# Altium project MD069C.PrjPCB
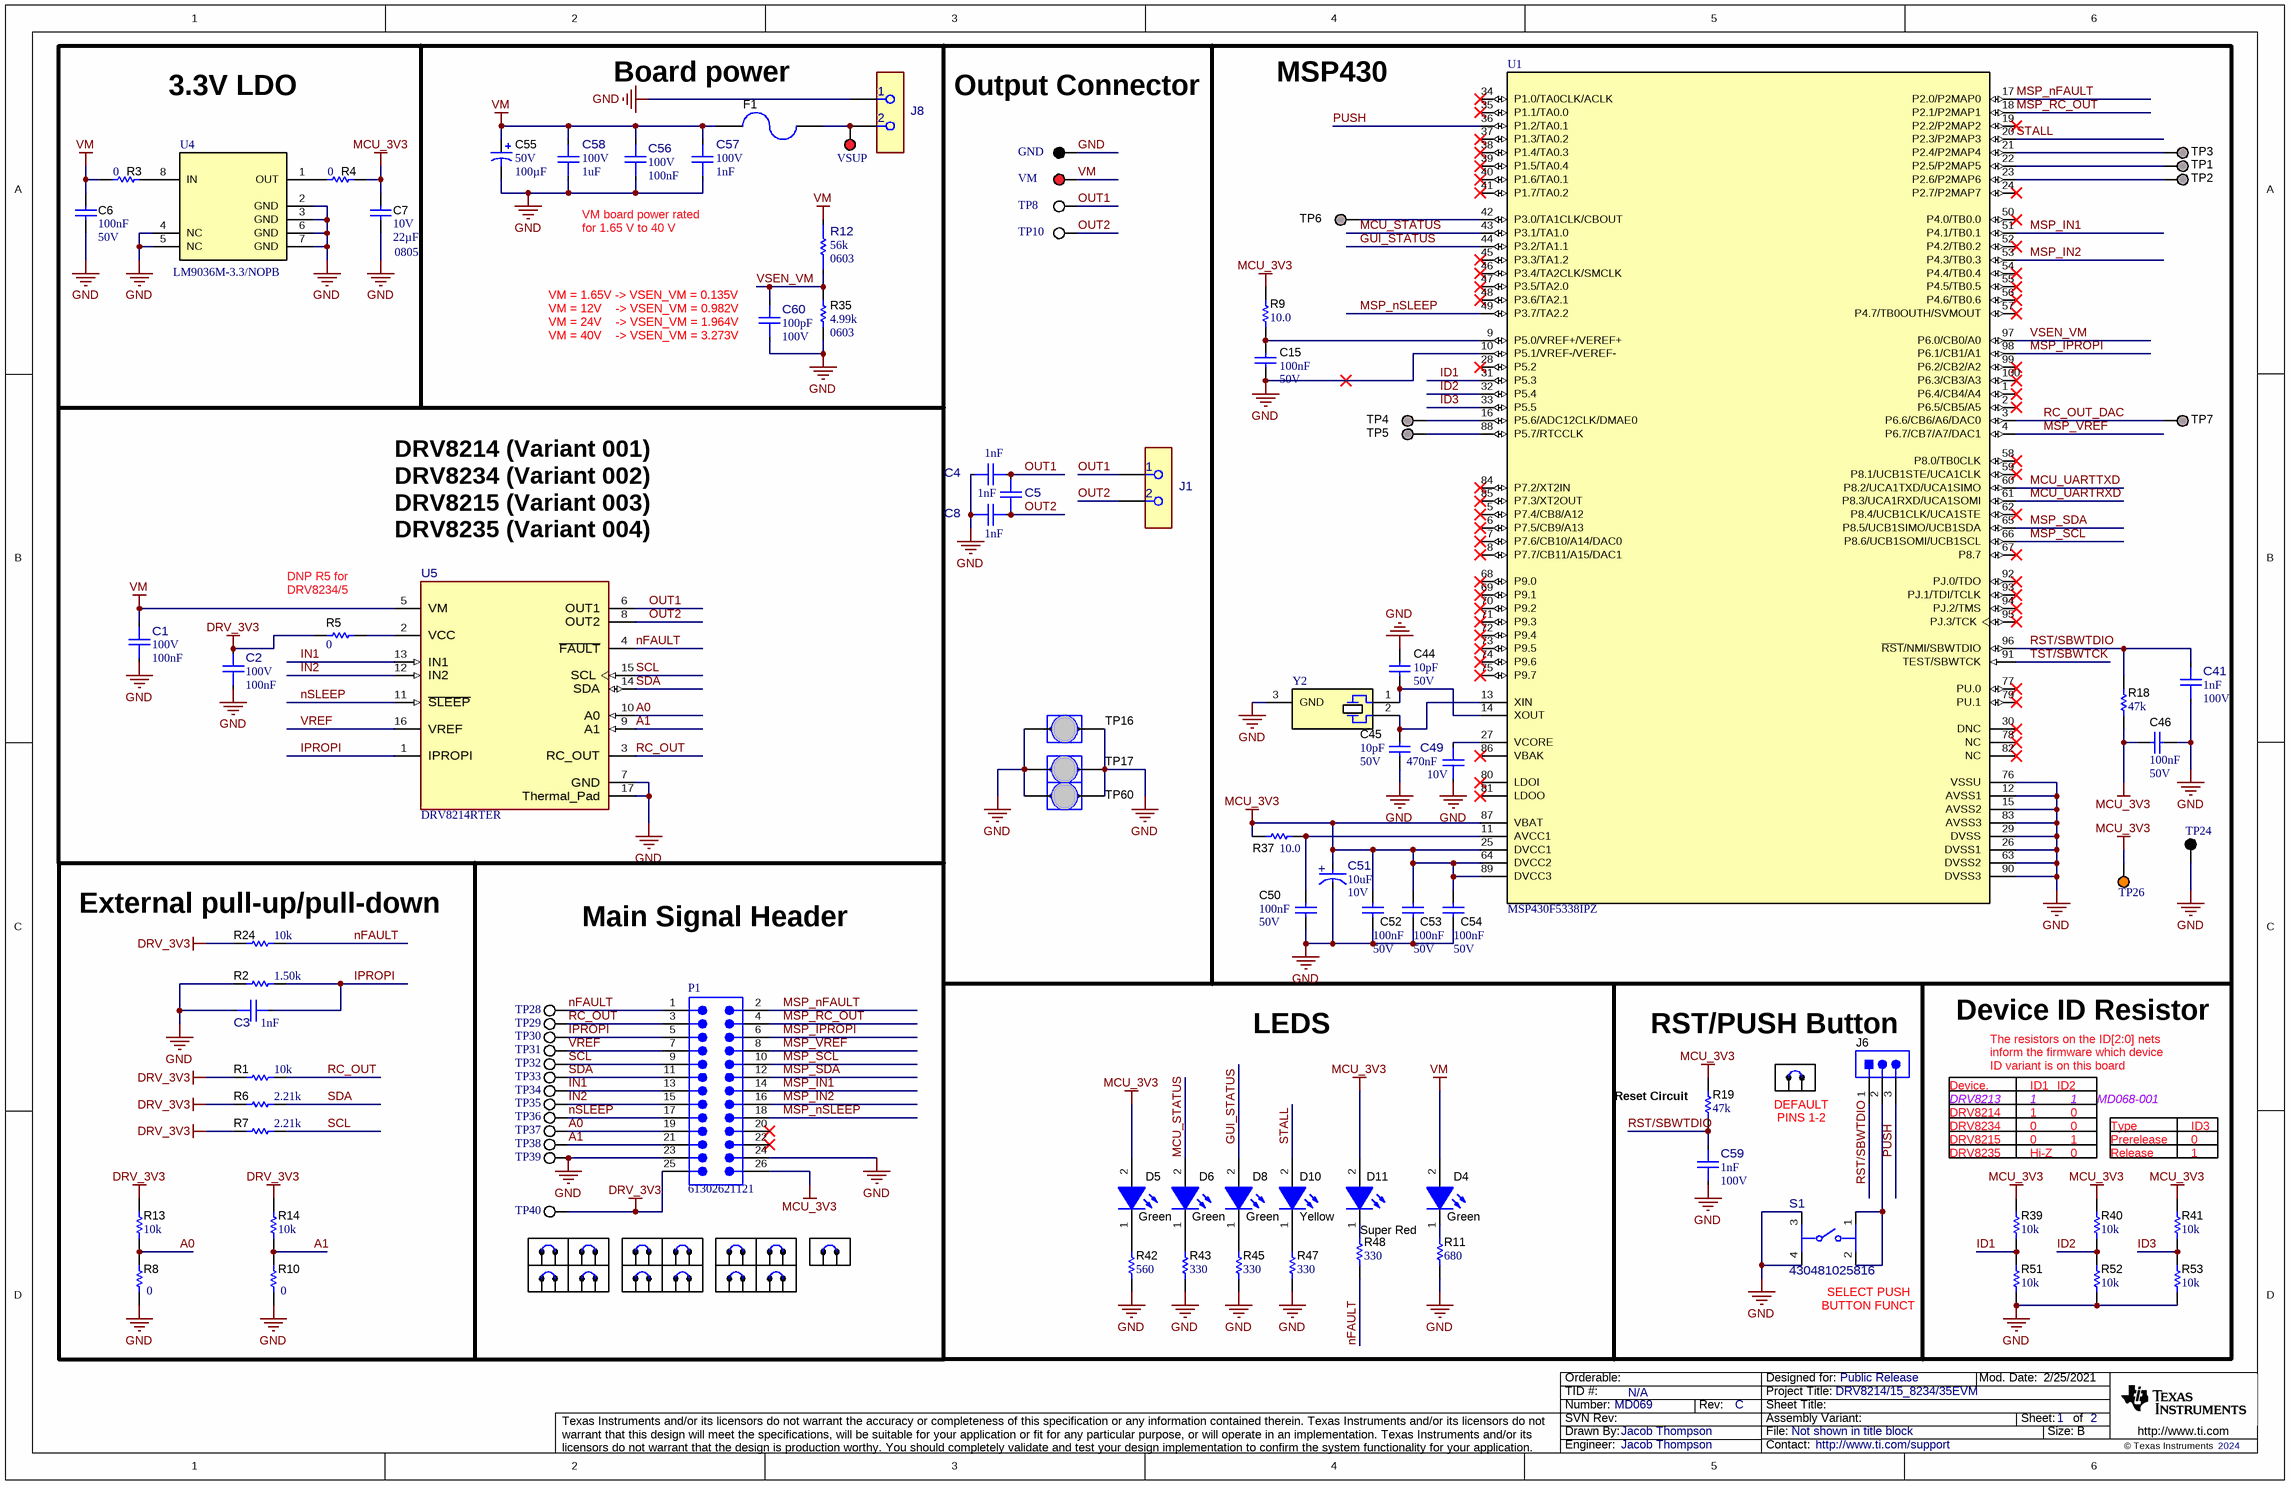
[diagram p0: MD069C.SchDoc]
TID: N/A; TechSupport: http://www.ti.com/support; SCH_Rev: C; PRJ_Title: DRV8214/15_8234/35EVM; PRJ_Number: MD069; PRJ_Engineer: Jacob Thompson; PRJ_Customer: Public Release; PCB_Rev: C; PCB_Layout: Jacob Thompson; CopyrightYear: 2024
3 sheets, 193 parts. Net scope: global (net labels, ports and power ports of the same name join across sheets).
Board file: MD069C.PcbDoc
Sheets:
  MD069C.SchDoc
  MD069C_Hardware.SchDoc
  MD069C_ezFET.SchDoc

## Sheet MD069C.SchDoc
size 431 x 279 mm; Date: Not shown in title block; ApprovedBy: Not shown in title block; CheckedBy: Not shown in title block; Author: Not shown in title block; CompanyName: Not shown in title block; DrawnBy: Jacob Thompson; Engineer: Not shown in title block; Organization: Not shown in title block; Address1: Not shown in title block; Address2: Not shown in title block; Address3: Not shown in title block; Address4: Not shown in title block; DocumentNumber: 2; Revision: C; SheetNumber: 1; SheetTotal: 2; PageSetup: Record=PageOptions¦CenterHorizontal=True¦CenterVertical=True¦PrintScale=1.00¦XCorrection=1.00¦YCorrection=1.00¦PrintKind=0¦BorderSize=5000000¦LeftOffset=0¦BottomOffset=0¦Orientation=2¦PaperLength=1000¦PaperWidth=1000¦Scale=100¦PaperSource=15¦PrintQuality=600¦MediaType=1¦DitherType=10¦PaperKind=Letter¦PrintScaleMode=1

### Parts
C1  VDC_V: 100V  Cap_F: 100nF  [FP-885012206120_0603-MFG]  (hidden comment: 885012206120)
C2  VDC_V: 100V  Cap_F: 100nF  [FP-885012206120_0603-MFG]  (hidden comment: 885012206120)
C3  value 1nF  [FP-885012006085_0603-MFG]  (hidden comment: 885012006085)
C4  value 1nF  [FP-885012006085_0603-MFG]  (hidden comment: 885012006085)
C5  value 1nF  [FP-885012006085_0603-MFG]  (hidden comment: 885012006085)
C6  Cap_F: 100nF  VDC_V: 50V  [0603]  (hidden comment: 885012206095)
C7  PackageReference: 0805  VDC_V: 10V  ValueDisplayed: 22µF  [0805_150]  (hidden comment: 885012107011)
C8  value 1nF  [FP-885012006085_0603-MFG]  (hidden comment: 885012006085)
C15  Cap_F: 100nF  VDC_V: 50V  [0603]  (hidden comment: 885012206095)
C41  ValueDisplayed: 1nF  VDC_V: 100V  [FP-885012006085_0603-MFG]  (hidden comment: 885012006085)
C44  VDC_V: 50V  ValueDisplayed: 10pF  [0402]  (hidden comment: 885012005055)
C45  VDC_V: 50V  ValueDisplayed: 10pF  [0402]  (hidden comment: 885012005055)
C46  Cap_F: 100nF  VDC_V: 50V  [0603]  (hidden comment: 885012206095)
C49  ValueDisplayed: 470nF  VDC_V: 10V  [FP-885012106008_0603-MFG]  (hidden comment: 885012106008)
C50  Cap_F: 100nF  VDC_V: 50V  [0603]  (hidden comment: 885012206095)
C51  ValueDisplayed: 10uF  VDC_V: 10V  [FP-875105240001_SMT_CAP_4MM3_4MM3-MFG]  (hidden comment: 875105240001)
C52  Cap_F: 100nF  VDC_V: 50V  [0603]  (hidden comment: 885012206095)
C53  Cap_F: 100nF  VDC_V: 50V  [0603]  (hidden comment: 885012206095)
C54  Cap_F: 100nF  VDC_V: 50V  [0603]  (hidden comment: 885012206095)
C55  VDC_V: 50V  ValueDisplayed: 100µF  [WCAP-ASLL_800x1050]  (hidden comment: 865060653010)
C56  VDC_V: 100V  Cap_F: 100nF  [FP-885012206120_0603-MFG]  (hidden comment: 885012206120)
C57  ValueDisplayed: 1nF  VDC_V: 100V  [FP-885012006085_0603-MFG]  (hidden comment: 885012006085)
C58  VDC_V: 100V  ValueDisplayed: 1uF  [FP-885012209069_1210-MFG]  (hidden comment: 885012209069)
C59  ValueDisplayed: 1nF  VDC_V: 100V  [FP-885012006085_0603-MFG]  (hidden comment: 885012006085)
C60  ValueDisplayed: 100pF  VDC_V: 100V  [FP-885012005080_0402-MFG]  (hidden comment: 885012005080)
D4  value Green  [WL-SMCW_GREEN]  (hidden comment: 150060VS75000)
D5  value Green  [WL-SMCW_GREEN]  (hidden comment: 150060VS75000)
D6  value Green  [WL-SMCW_GREEN]  (hidden comment: 150060VS75000)
D8  value Green  [WL-SMCW_GREEN]  (hidden comment: 150060VS75000)
D10  value Yellow  [WL-SMCW_YELLOW]  (hidden comment: 150060YS75000)
D11  value Super Red  [WL-SMCW_RED]  (hidden comment: 150060SS75000)
F1  0463030.ER  [Fuse_0463]  (value not drawn)
GND  5011  [Keystone5011]  (value not drawn)
J1  691250610002  [FP-691250610002_CONN_TERM_BLOCK2-MFG]  (value not drawn)
J6  61300311121  [WURTH_61300311121]  (value not drawn)
J8  691250610002  [FP-691250610002_CONN_TERM_BLOCK2-MFG]  (value not drawn)
P1  61302621121  [61302621121]
R1  ValueDisplayed: 10k  [0603]  (hidden comment: RC0603JR-0710KL)
R2  ValueDisplayed: 1.50k  [0603S]  (hidden comment: ERJ-3EKF1501V)
R3  value 0  [0603L]  (hidden comment: Resistor)
R4  value 0  [0603L]  (hidden comment: Resistor)
R5  ValueDisplayed: 0  [0402S]  (hidden comment: RC0402JR-070RL)
R6  ValueDisplayed: 2.21k  [0402]  (hidden comment: CRCW04022K21FKED)
R7  ValueDisplayed: 2.21k  [0402]  (hidden comment: CRCW04022K21FKED)
R8  value 0  [0603L]  (hidden comment: Resistor)
R9  ValueDisplayed: 10.0  [0402]  (hidden comment: CRCW040210R0FKED)
R10  value 0  [0603L]  (hidden comment: Resistor)
R11  ValueDisplayed: 680  [0402]  (hidden comment: CRCW0402680RJNED)
R12  value 56k  PackageReference: 0603  [FP-ERJ-3EKF5602V_0603-MFG]  (hidden comment: ERJ-3EKF5602V)
R13  ValueDisplayed: 10k  [0603]  (hidden comment: RC0603JR-0710KL)
R14  ValueDisplayed: 10k  [0603]  (hidden comment: RC0603JR-0710KL)
R18  ValueDisplayed: 47k  [0402]  (hidden comment: CRCW040247K0JNED)
R19  ValueDisplayed: 47k  [0402]  (hidden comment: CRCW040247K0JNED)
R24  ValueDisplayed: 10k  [0603]  (hidden comment: RC0603JR-0710KL)
R35  ValueDisplayed: 4.99k  PackageReference: 0603  [0603L]  (hidden comment: CRCW06034K99FKEA)
R37  ValueDisplayed: 10.0  [0402]  (hidden comment: CRCW040210R0FKED)
R39  ValueDisplayed: 10k  [0603]  (hidden comment: RC0603JR-0710KL)
R40  ValueDisplayed: 10k  [0603]  (hidden comment: RC0603JR-0710KL)
R41  ValueDisplayed: 10k  [0603]  (hidden comment: RC0603JR-0710KL)
R42  ValueDisplayed: 560  [0603]  (hidden comment: RC0603JR-07560RL)
R43  ValueDisplayed: 330  [0603]  (hidden comment: CRCW0603330RJNEA)
R45  ValueDisplayed: 330  [0603]  (hidden comment: CRCW0603330RJNEA)
R47  ValueDisplayed: 330  [0603]  (hidden comment: CRCW0603330RJNEA)
R48  ValueDisplayed: 330  [0603]  (hidden comment: CRCW0603330RJNEA)
R51  ValueDisplayed: 10k  [0603]  (hidden comment: RC0603JR-0710KL)
R52  ValueDisplayed: 10k  [0603]  (hidden comment: RC0603JR-0710KL)
R53  ValueDisplayed: 10k  [0603]  (hidden comment: RC0603JR-0710KL)
S1  430481025816  [FP-430481025816_SMT_SW_6MM2_6MM2-MFG]
SH-J1  60900213421  [Wurth_60900213421]  (value not drawn)
SH-J2  60900213421  [Wurth_60900213421]  (value not drawn)
SH-J3  60900213421  [Wurth_60900213421]  (value not drawn)
SH-J4  60900213421  [Wurth_60900213421]  (value not drawn)
SH-J5  60900213421  [Wurth_60900213421]  (value not drawn)
SH-J6  60900213421  [Wurth_60900213421]  (value not drawn)
SH-J7  60900213421  [Wurth_60900213421]  (value not drawn)
SH-J8  60900213421  [Wurth_60900213421]  (value not drawn)
SH-J9  60900213421  [Wurth_60900213421]  (value not drawn)
SH-J10  60900213421  [Wurth_60900213421]  (value not drawn)
SH-J11  60900213421  [Wurth_60900213421]  (value not drawn)
SH-J12  60900213421  [Wurth_60900213421]  (value not drawn)
SH-J19  60900213421  [Wurth_60900213421]  (value not drawn)
SH-J36  60900213421  [Wurth_60900213421]  (value not drawn)
TP1  TP_H0.45P0.75  [TP_H045P075]  (value not drawn)  (no BOM)
TP2  TP_H0.45P0.75  [TP_H045P075]  (value not drawn)  (no BOM)
TP3  TP_H0.45P0.75  [TP_H045P075]  (value not drawn)  (no BOM)
TP4  TP_H0.45P0.75  [TP_H045P075]  (value not drawn)  (no BOM)
TP5  TP_H0.45P0.75  [TP_H045P075]  (value not drawn)  (no BOM)
TP6  TP_H0.45P0.75  [TP_H045P075]  (value not drawn)  (no BOM)
TP7  TP_H0.45P0.75  [TP_H045P075]  (value not drawn)  (no BOM)
TP8  5012  [Keystone5012]  (value not drawn)
TP10  5012  [Keystone5012]  (value not drawn)
TP16  Jumper_2p  [Harwin_D3082-05]  (value not drawn)
TP17  Jumper_2p  [Harwin_D3082-05]  (value not drawn)
TP24  5011  [Keystone5011]  (value not drawn)
TP26  5003  [Keystone5003]  (value not drawn)
TP28  5002  [Keystone5002]  (value not drawn)
TP29  5002  [Keystone5002]  (value not drawn)
TP30  5002  [Keystone5002]  (value not drawn)
TP31  5002  [Keystone5002]  (value not drawn)
TP32  5002  [Keystone5002]  (value not drawn)
TP33  5002  [Keystone5002]  (value not drawn)
TP34  5002  [Keystone5002]  (value not drawn)
TP35  5002  [Keystone5002]  (value not drawn)
TP36  5002  [Keystone5002]  (value not drawn)
TP37  5002  [Keystone5002]  (value not drawn)
TP38  5002  [Keystone5002]  (value not drawn)
TP39  5002  [Keystone5002]  (value not drawn)
TP40  5002  [Keystone5002]  (value not drawn)
TP60  Jumper_2p  [Harwin_D3082-05]  (value not drawn)
U1  MSP430F5338IPZ  [PZT0100A_N]
U4  LM9036M-3.3/NOPB  [D0008A_N]
U5  DRV8214RTER  [RTE0016C-MFG]
VM  5010  [Keystone5010]  (value not drawn)
VSUP  5010  [Keystone5010]  (value not drawn)
Y2  MS3V-T1R 32.768KHZ +/-20PPM 12.5PF  [XTAL_MS3V-T1R]  (value not drawn)

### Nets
DRV_3V3: C2.2 P1.25 R1.1 R5.1 R6.1 R7.1 R13.2 R14.2 R24.1 TP40.1
GND: C1.1 C2.1 C3.1 C4.1 C6.2 C7.2 C8.1 C15.2 C41.1 C44.1 C45.2 C46.1 C49.1 C50.2 C51.1(CATHODE) C52.2 C53.2 C54.2 C55.2(-) C56.1 C57.1 C58.1 C59.1 C60.1 GND.1 J8.1 P1.23 P1.24 R2.2 R8.1 R10.1 R11.1 R35.1 R42.1 R43.1 R45.1 R47.1 R51.2 R52.2 R53.2 S1.3 S1.4 TP16.1 TP16.2 TP17.1 TP17.2 TP24.1 TP39.1 TP60.1 TP60.2 U1.10(P5.1/VREF-/VEREF-) U1.12(AVSS1) U1.15(AVSS2) U1.26(DVSS1) U1.29(DVSS) U1.63(DVSS2) U1.76(VSSU) U1.83(AVSS3) U1.90(DVSS3) U4.2(GND) U4.3(GND) U4.4(NC) U4.5(NC) U4.6(GND) U4.7(GND) U5.7(GND) U5.17(Thermal_Pad) Y2.3(GND)
MCU_3V3: C7.1 C46.2 C51.2(ANODE) C52.1 C53.1 C54.1 D5.2(A) D11.2(A) P1.26 R4.1 R9.2 R18.1 R19.2 R37.1 R39.1 R40.1 R41.1 TP26.1 U1.25(DVCC1) U1.64(DVCC2) U1.87(VBAT) U1.89(DVCC3)
VM: C1.2 C6.1 C55.1(+) C56.2 C57.2 C58.2 D4.2(A) F1.2 R3.2 R12.2 U5.5(VM) VM.1
A0: P1.19 R8.2 R13.1 TP37.1 U5.10(A0)
A1: P1.21 R10.2 R14.1 TP38.1 U5.9(A1)
GUI_STATUS: D8.2(A) U1.44(P3.2/TA1.1)
ID1: R39.2 R51.1 U1.31(P5.3)
ID2: R40.2 R52.1 U1.32(P5.4)
ID3: R41.2 R53.1 U1.33(P5.5)
IN1: P1.13 TP34.1 U5.13(IN1)
IN2: P1.15 TP35.1 U5.12(IN2)
IPROPI: C3.2 P1.5 R2.1 TP30.1 U5.1(IPROPI)
MCU_STATUS: D6.2(A) U1.43(P3.1/TA1.0)
MCU_UARTRXD: U1.61(P8.3/UCA1RXD/UCA1SOMI)
MCU_UARTTXD: U1.60(P8.2/UCA1TXD/UCA1SIMO)
MSP_IN1: P1.14 U1.51(P4.1/TB0.1)
MSP_IN2: P1.16 U1.53(P4.3/TB0.3)
MSP_IPROPI: P1.6 U1.98(P6.1/CB1/A1)
MSP_nFAULT: P1.2 U1.17(P2.0/P2MAP0)
MSP_nSLEEP: P1.18 U1.49(P3.7/TA2.2)
MSP_RC_OUT: P1.4 U1.18(P2.1/P2MAP1)
MSP_SCL: P1.10 U1.66(P8.6/UCB1SOMI/UCB1SCL)
MSP_SDA: P1.12 U1.65(P8.5/UCB1SIMO/UCB1SDA)
MSP_VREF: P1.8 U1.4(P6.7/CB7/A7/DAC1)
nFAULT: P1.1 R24.2 R48.1 TP28.1 U5.4(~{FAULT})
nSLEEP: P1.17 TP36.1 U5.11(~{SLEEP})
OUT1: C4.2 C5.2 J1.1 TP8.1 U5.6(OUT1)
OUT2: C5.1 C8.2 J1.2 TP10.1 U5.8(OUT2)
PUSH: J6.3 U1.36(P1.2/TA0.1)
RC_OUT: P1.3 R1.2 TP29.1 U5.3(RC_OUT)
RC_OUT_DAC: TP7.1 U1.3(P6.6/CB6/A6/DAC0)
RST/SBWTDIO: C41.2 C59.2 J6.1 R18.2 R19.1 U1.96(~{RST}/NMI/SBWTDIO)
SCL: P1.9 R7.2 TP32.1 U5.15(SCL)
SDA: P1.11 R6.2 TP33.1 U5.14(SDA)
STALL: D10.2(A) U1.20(P2.3/P2MAP3)
TST/SBWTCK: U1.91(TEST/SBWTCK)
VREF: P1.7 TP31.1 U5.16(VREF)
VSEN_VM: C60.2 R12.1 R35.2 U1.97(P6.0/CB0/A0)
NetC15_1: C15.1 R9.1 U1.9(P5.0/VREF+/VEREF+)
NetC44_2: C44.2 U1.14(XOUT) Y2.1
NetC45_1: C45.1 U1.13(XIN) Y2.2
NetC49_2: C49.2 U1.27(VCORE)
NetC50_1: C50.1 R37.2 U1.11(AVCC1)
NetD4_1: D4.1(K) R11.2
NetD5_1: D5.1(K) R42.2
NetD6_1: D6.1(K) R43.2
NetD8_1: D8.1(K) R45.2
NetD10_1: D10.1(K) R47.2
NetD11_1: D11.1(K) R48.2
NetF1_1: F1.1 J8.2 VSUP.1
NetJ6_2: J6.2 S1.1 S1.2
NetR3_1: R3.1 U4.8(IN)
NetR4_2: R4.2 U4.1(OUT)
NetR5_2: R5.2 U5.2(VCC)
NetTP1_1: TP1.1 U1.22(P2.5/P2MAP5)
NetTP2_1: TP2.1 U1.23(P2.6/P2MAP6)
NetTP3_1: TP3.1 U1.21(P2.4/P2MAP4)
NetTP4_1: TP4.1 U1.16(P5.6/ADC12CLK/DMAE0)
NetTP5_1: TP5.1 U1.88(P5.7/RTCCLK)
NetTP6_1: TP6.1 U1.42(P3.0/TA1CLK/CBOUT)

Not connected (* = marked no-connect by the designer): P1 20* 22*; U1 1(P6.4/CB4/A4)* 2(P6.5/CB5/A5)* 5(P7.4/CB8/A12)* 6(P7.5/CB9/A13)* 7(P7.6/CB10/A14/DAC0)* 8(P7.7/CB11/A15/DAC1)* 19(P2.2/P2MAP2)* 24(P2.7/P2MAP7)* 28(P5.2)* 30(DNC)* 34(P1.0/TA0CLK/ACLK)* 35(P1.1/TA0.0)* 37(P1.3/TA0.2)* 38(P1.4/TA0.3)* 39(P1.5/TA0.4)* 40(P1.6/TA0.1)* 41(P1.7/TA0.2)* 45(P3.3/TA1.2)* 46(P3.4/TA2CLK/SMCLK)* 47(P3.5/TA2.0)* 48(P3.6/TA2.1)* 50(P4.0/TB0.0)* 52(P4.2/TB0.2)* 54(P4.4/TB0.4)* 55(P4.5/TB0.5)* 56(P4.6/TB0.6)* 57(P4.7/TB0OUTH/SVMOUT)* 58(P8.0/TB0CLK)* 59(P8.1/UCB1STE/UCA1CLK)* 62(P8.4/UCB1CLK/UCA1STE)* 67(P8.7)* 68(P9.0)* 69(P9.1)* 70(P9.2)* 71(P9.3)* 72(P9.4)* 73(P9.5)* 74(P9.6)* 75(P9.7)* 77(PU.0)* 78(NC)* 79(PU.1)* 80(LDOI)* 81(LDOO)* 82(NC)* 84(P7.2/XT2IN)* 85(P7.3/XT2OUT)* 86(VBAK)* 92(PJ.0/TDO)* 93(PJ.1/TDI/TCLK)* 94(PJ.2/TMS)* 95(PJ.3/TCK)* 99(P6.2/CB2/A2)* 100(P6.3/CB3/A3)*

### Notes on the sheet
- 3.3V LDO
- Board power
- Output Connector
- MSP430
- VM board power rated for 1.65 V to 40 V
- (near C60) VM = 1.65V -> VSEN_VM = 0.135V
  VM = 12V    -> VSEN_VM = 0.982V
  VM = 24V    -> VSEN_VM = 1.964V
  VM = 40V    -> VSEN_VM = 3.273V
- DRV8214 (Variant 001)
  DRV8234 (Variant 002)
  DRV8215 (Variant 003)
  DRV8235 (Variant 004)
- DNP R5 for DRV8234/5
- (near R24) External pull-up/pull-down
- Main Signal Header
- LEDS
- RST/PUSH Button
- Device ID Resistor
- (near R19) Reset Circuit
- (near SH-J5) DEFAULT
- Device.
- DRV8213
- The resistors on the ID[2:0] nets inform the firmware which device ID variant is on this board
- ID1
- 1
- ID2
- MD068-001
- (near SH-J5) PINS 1-2
- DRV8214
- DRV8234
- DRV8215
- DRV8235
- 0
- Hi-Z
- Type
- Prerelease
- Release
- ID3
- (near S1) SELECT PUSH
- BUTTON FUNCT

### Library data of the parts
C1 C2 C56 = CMP-0097294-1: 0.1 µF ±10% 100V Ceramic Capacitor X7R 0603 (1608 Metric); Manufacturer: Wurth Electronics; TempCo: 15%; SizeZ_mm: 0.87mm; Value: 100nF; AEC Qualified: No
C3-C5 C8 = CMP-0097311-1: 1000 pF ±5% 100V Ceramic Capacitor C0G, NP0 0603 (1608 Metric); Manufacturer: Wurth Electronics; TempCo: 30ppm/°C; SizeZ_mm: 0.87mm; AEC Qualified: No
C6 C15 C46 C50 C52-C54 = CMP-0006837-4: CAP, CERM, 0.1 uF, 50 V, +/- 10%, X7R, 0603; Manufacturer: Wurth Elektronik; TaMin_C: -55°C; Polarized: N; SizeAreaWB_mm2: 4.68; Value1: Unknown; U/M: EA; Value: 0.1uF; TaMax_C: 125°C; SizeZ_mm: 1; SizeX_mm: 1.6; SizeY_mm: 0.8; SizeArea_mm2: 1.28; AEC Category: Q200
C7 = CMP-0078153-1: CAP, CERM, 22 µF, 10 V,+/- 20%, X5R, 0805; Manufacturer: Wurth Elektronik; TaMin_C: -55°C; Polarized: N; SizeAreaWB_mm2: 6.75; U/M: EA; Value: 22uF; TaMax_C: 85°C; SizeZ_mm: 1.5; SizeX_mm: 2; SizeY_mm: 1.25; SizeArea_mm2: 2.5; AEC Category: Q200
C41 C57 C59 = CMP-0097311-1: 1000 pF ±5% 100V Ceramic Capacitor C0G, NP0 0603 (1608 Metric); Manufacturer: Wurth Electronics; TempCo: 30ppm/°C; SizeZ_mm: 0.87mm; AEC Qualified: No; Value: 1nF
C44 C45 = CMP-0006215-2: CAP, CERM, 10 pF, 50 V, +/- 5%, C0G/NP0, 0402; Manufacturer: Wurth Elektronik; TaMin_C: -55°C; Polarized: N; SizeAreaWB_mm2: 3; Value1: Unknown; U/M: EA; Value: 10pF; TaMax_C: 125°C; SizeZ_mm: 0.6; SizeX_mm: 1; SizeY_mm: 0.5; AEC Category: Q200
C49 = CMP-0097299-1: 0.47 µF ±20% 10V Ceramic Capacitor X5R 0603 (1608 Metric); Manufacturer: Wurth Electronics; Value: 470nF; AEC Qualified: No; TempCo: 15%; SizeZ_mm: 0.87mm
C51 = CMP-0097340-1: Alum. Polymer Cap 10µF 10V 5.5mmV-Chip WCAP-PSLP Series Lifetime 2000h +105°C; Manufacturer: Wurth Electronics; Life: 2000Hours; Dissipation Factor: 8%; Esr: 45m; IRMS_A: 1.2A; Tolerance_%: 20%; AEC Qualified: No; SizeZ_mm: 5.5mm; Leakage Current: 300uA
C55 = CMP-0081644-1: CAP, AL, 100 µF, 50 V, +/- 20%, SMD; Manufacturer: Wurth Elektronik; IRMS_A: 350mA; SizeAreaWB_mm2: 106.09; SizeArea_mm2: 68.89; AEC Qualified: N; AEC Category: Q200; Value: 100uF; TaMax_C: 105°C; SizeZ_mm: 10.5; Polarized: Y; TaMin_C: -55°C; SizeY_mm: 8.3; U/M: EA; CompType: Capacitor; Cap_Case: 8X10.5mm
C58 = CMP-0097312-1: 1 µF ±10% 100V Ceramic Capacitor X7R 1210 (3225 Metric); Manufacturer: Wurth Electronics; AEC Qualified: No; SizeZ_mm: 2.2mm; Cap_F: 1µF; Value: 1µF; TempCo: 15%
C60 = CMP-0097308-1: 100 pF ±5% 100V Ceramic Capacitor C0G, NP0 0402 (1005 Metric); Manufacturer: Wurth Electronics; Value: 100pF; SizeZ_mm: 0.55mm; TempCo: 30ppm/°C; AEC Qualified: No
D4-D6 D8 = CMP-0002894-2: LED, Green, SMD; Manufacturer: Wurth Elektronik; Type: AlInGaP; Value2: 2V; Io_A: 20mA; Value1: W
D10 = CMP-0002892-3: LED, Yellow, SMD; Manufacturer: Wurth Elektronik; Value1: W; Vf_V: 2V; Type: AlInGaP; Io_A: 20mA
D11 = CMP-0002893-1: LED, Super Red, SMD; Manufacturer: Wurth Elektronik; Io_A: 20mA; Value1: W; U/M: EA; Vf_V: 1.9V; Type: AlInGaP
F1 = CMP-0077200-3: Fuse, 30 A, 250 VAC, 100 VDC, SMD; Manufacturer: Littelfuse; VAC_V: 250V; SizeAreaWB_mm2: 61.952; Rtyp_Ohm: 1.93m; SizeArea_mm2: 31.512; MeltingTyp: 916; Irating_A: 30A; SizeZ_mm: 3.12; VDC_V: 100V; SizeX_mm: 10.1; Interrupt_AC: 100A; Interrupt_DC: 50A; Fuse Speed: Fast; Fuse Technology: Board Mount; TaMax_C: 125°C; TaMin_C: -55°C
GND TP24 = CMP-0055148-2: Test Point, Multipurpose, Black, TH; Manufacturer: Keystone Electronics; PartNumber: 36-5011-ND; CNHeader: FALSE; Green_Lifecycle: Active; Green_REACh: Passed; ContactFinish: Silver; CT: TRUE
J1 J8 = CMP-0093233-2: 2 Position Wire to Board Terminal Block Horizontal with Board 0.250" (6.35mm) Through Hole; Manufacturer: Wurth Electronics; Current_A: 32A; Conn Gender: Female; Row_Count: 1; ContactFinish: Zinc; SizeZ_mm: 21.6mm; Max Wire Gauge: 10; Min Wire Gauge: 30; Voltage_V: 450V; AEC Qualified: No; Is Female: yes
J6 = CMP-0054796-4: Header, 2.54 mm, 3x1, Gold, TH; Manufacturer: Wurth Elektronik; Green_Lifecycle: Active; Green_REACh: Passed; CT: FALSE; CNHeader: TRUE
P1 = CMP-1502-01114-2: Header, 2.54mm, 13x2, Gold, TH; NexarPartId: 32855565; Manufacturer: Wurth Elektronik; Contact Resistance: 20mΩ; Gender: Male; Connector Type: Male Pin; Number of Positions: 26; Current Rating: 3A; Operating Supply Voltage: 250V
R1 R13 R14 R24 R39-R41 R51-R53 = CMP-0025886-5: RES, 10 k, 5%, 0.1 W, 0603; Manufacturer: Yageo; Power_W: 100mW; TempCo: 100 ppm/C; Value_Code: 10k0; Value: 10k; EIA_Code: E24; SizeX_mm: 1.6; SizeY_mm: 0.8; SizeZ_mm: 1; Value2: 0.1W; SizeArea_mm2: 1.28; AEC Qualified: N; VDC_V: 75V; AEC Category: Q200; SizeAreaWB_mm2: 4.68
R2 = CMP-0022689-3: RES, 1.50 k, 1%, 0.1 W, 0603; Manufacturer: Panasonic; Power_W: 100mW; TempCo: 100 ppm/C; Value_Code: 1k50; U/M: EA; Value: 1.50k; EIA_Code: E96; Res_ohm: 1.5k; SizeX_mm: 1.6; SizeY_mm: 0.8; SizeZ_mm: 1; Value2: 0.1W; SizeArea_mm2: 1.28; VDC_V: 75V; AEC Category: Q200
R3 R4 R8 R10 = CMP-0025697-4: RES, 0, 5%, 0.1 W, AEC-Q200 Grade 0, 0603; PartNumber: CRCW06030000Z0EA; Manufacturer: Vishay-Dale; Value_Code: 0000; Power_W: 100mW; Value2: 0.1W; VDC_V: 75V; TempCo: 200 ppm/C; EIA_Code: E24; AEC Category: Q200; AEC Qualified: Y; SizeArea_mm2: 1.28; SizeX_mm: 1.6; SizeY_mm: 0.8; SizeZ_mm: 1
R5 = CMP-0027004-2: RES, 0, 5%, 0.063 W, 0402; Manufacturer: Yageo America; Power_W: 63mW; TempCo: 200 ppm/C; Value_Code: 0000; U/M: EA; Value: 0; EIA_Code: E24; SizeX_mm: 1; SizeY_mm: 0.5; SizeZ_mm: 0.6; Value2: 0.063W; VDC_V: 50V; AEC Category: Q200
R6 R7 = CMP-0026232-2: RES, 2.21 k, 1%, 0.063 W, AEC-Q200 Grade 0, 0402; Manufacturer: Vishay-Dale; Power_W: 63mW; TempCo: 100 ppm/C; Value_Code: 2k21; Value: 2.21k; EIA_Code: E96; SizeX_mm: 1; SizeY_mm: 0.5; SizeZ_mm: 0.6; Value2: 0.063W; AEC Qualified: Y; VDC_V: 50V; AEC Category: Q200; AEC Grade: 0
R9 R37 = CMP-0025963-3: RES, 10.0, 1%, 0.063 W, AEC-Q200 Grade 0, 0402; Manufacturer: Vishay-Dale; Power_W: 63mW; TempCo: 100 ppm/C; Value_Code: 10R0; Value: 10.0; EIA_Code: E96; Res_ohm: 10; SizeX_mm: 1; SizeY_mm: 0.5; SizeZ_mm: 0.6; Value2: 0.063W; AEC Qualified: Y; VDC_V: 50V; AEC Category: Q200; AEC Grade: 0
R11 = CMP-0026962-3: RES, 680, 5%, 0.063 W, AEC-Q200 Grade 0, 0402; Manufacturer: Vishay-Dale; Power_W: 63mW; TempCo: 200 ppm/C; Value_Code: 680R; Value: 680; EIA_Code: E24; SizeX_mm: 1; SizeY_mm: 0.5; SizeZ_mm: 0.6; Value2: 0.063W; AEC Qualified: Y; VDC_V: 50V; AEC Category: Q200; AEC Grade: 0
R12 = CMP-0094677-1: 56 kOhms ±1% 0.1W, 1/10W Chip Resistor 0603 (1608 Metric) Automotive AEC-Q200 Thick Film; Manufacturer: Panasonic; AEC Grade: Grade 0; VDC_V: 75V; TempCo: 100ppm/°C; Power_W: 100mW; SizeZ_mm: 0.55mm; AEC Qualified: Yes
R18 R19 = CMP-0026935-3: RES, 47 k, 5%, 0.063 W, AEC-Q200 Grade 0, 0402; Manufacturer: Vishay-Dale; Power_W: 63mW; TempCo: 200 ppm/C; Value_Code: 47k0; Value: 47k; EIA_Code: E24; SizeX_mm: 1; SizeY_mm: 0.5; SizeZ_mm: 0.6; Value2: 0.063W; AEC Qualified: Y; VDC_V: 50V; AEC Category: Q200; AEC Grade: 0
R35 = CMP-0022458-4: RES, 4.99 k, 1%, 0.1 W, AEC-Q200 Grade 0, 0603; Manufacturer: Vishay-Dale; Value: 4.99k; Value_Code: 4k99; Power_W: 100mW; Value2: 0.1W; VDC_V: 75V; TempCo: 100 ppm/C; EIA_Code: E96; SizeX_mm: 1.6; SizeY_mm: 0.8; SizeZ_mm: 1; SizeArea_mm2: 1.28; AEC Qualified: Y; AEC Category: Q200; AEC Grade: 0
R42 = CMP-0025930-5: RES, 560, 5%, 0.1 W, 0603; Manufacturer: Yageo; Power_W: 100mW; TempCo: 100 ppm/C; Value_Code: 560R; Value: 560; EIA_Code: E24; SizeX_mm: 1.6; SizeY_mm: 0.8; SizeZ_mm: 1; Value2: 0.1W; SizeArea_mm2: 1.28; AEC Qualified: N; VDC_V: 75V; AEC Category: Q200; SizeAreaWB_mm2: 4.68
R43 R45 R47 R48 = CMP-0025785-4: RES, 330, 5%, 0.1 W, AEC-Q200 Grade 0, 0603; Manufacturer: Vishay-Dale; Power_W: 100mW; TempCo: 200 ppm/C; Value_Code: 330R; Value: 330; EIA_Code: E24; SizeX_mm: 1.6; SizeY_mm: 0.8; SizeZ_mm: 1; Value2: 0.1W; SizeArea_mm2: 1.28; AEC Qualified: Y; VDC_V: 75V; AEC Category: Q200; AEC Grade: 0
S1 = CMP-0097347-1: Tactile Switch SPST-NO Top Actuated Surface Mount; Manufacturer: Wurth Electronics; VDC_V: 12V; Electromechanical Life: 1000000Cycles; SizeZ_mm: 2.7mm; Coil Resistance_ohm: 100mΩ; Operating Force: 160gf; AEC Qualified: No; Contact Current Rating: 50mA
SH-J1-SH-J12 SH-J19 SH-J36 = CMP-0003761-2: Shunt, 2.54mm, Gold, Black; Manufacturer: Wurth Elektronik
TP1-TP7 = CMP-0003719-1: Testpoint; Manufacturer: Texas Instruments; CompType: Pad
TP8 TP10 = CMP-0055149-2: Test Point, Multipurpose, White, TH; Manufacturer: Keystone Electronics; ContactFinish: Silver; CT: TRUE; CNHeader: FALSE; Green_Lifecycle: Active; Green_REACh: Passed
TP16 TP17 TP60 = CMP-0075110-1: 1mm Uninsulated Shorting Plug, 10.16mm spacing, TH; Manufacturer: Harwin; PartNumber: D3082-05; CompType: Jumper Wire; CNHeader: False; Green_Lifecycle: Active; Green_REACh: Passed
TP26 = CMP-0055140-2: Test Point, Miniature, Orange, TH; Manufacturer: Keystone Electronics; CNHeader: FALSE; Green_Lifecycle: Active; Green_REACh: Passed; ContactFinish: Silver; CT: TRUE
TP28-TP40 = CMP-0055139-2: Test Point, Miniature, White, TH; Manufacturer: Keystone Electronics; ContactFinish: Silver; Green_REACh: Passed; CT: TRUE; Green_Lifecycle: Active; CNHeader: FALSE
U1 = CMP-0038879-1: 20 MHz Mixed Signal Microcontroller with 256 KB Flash, 18432 B SRAM and 74 GPIOs, -40 to 85 degC, 100-pin QFP (PZ), Green (RoHS & no Sb/Br); Manufacturer: Texas Instruments; Flash(KB): 256; USCI_B (I2C & SPI): 2; ADC Channels: 16; Comparators: Yes; Frequency(MHz): 20; DMA: 3; SRAM(B): 18432; Multiplier: 32x32; GPIO: 74; Timers - 16-bit: 4; SubFamily: 5 Series; ADC: 12-bit SAR
U4 = CMP-0070570-1: Ultra-Low Quiescent Current Voltage Regulator, 8-pin Narrow SOIC, Pb-Free; Manufacturer: Texas Instruments; PackageTopMarking: NSZXTT*LM903*6M-3; PowerWise: N; CompType: LDO IC
U5 = CMP-0097573-1: 2-A Brushed DC Motor Driver with Stall Detection, Ripple Counting and Speed Regulation; Manufacturer: Texas Instruments; Standoff Height: 0mm; SizeZ_mm: 0.8mm; Number Of Outputs: 2; TJmax_C: +150°C; TaMin_C: -40°C; AEC Qualified: No; Switching Frequency: 200kHz; Min Supply Voltage: 1.65V; Max Supply Voltage: 11V; TaMax_C: +125°C
VM VSUP = CMP-0055147-2: Test Point, Multipurpose, Red, TH; Manufacturer: Keystone Electronics; PartNumber: 36-5010-ND; CNHeader: FALSE; Green_Lifecycle: Active; Green_REACh: Passed; ContactFinish: Silver; CT: TRUE
Y2 = CMP-0004566-4: Crystal, 32.768 kHz, 12.5pF, SMD; Manufacturer: Micro Crystal AG; TaMin_C: -40°C; TaMax_C: 85°C; AEC Category: Q200; AEC Qualified: N; Frequency Tolerance: 20 ppm

## Sheet MD069C_Hardware.SchDoc
size 431 x 279 mm; Date: Not shown in title block; ApprovedBy: Not shown in title block; CheckedBy: Not shown in title block; Author: Not shown in title block; CompanyName: Not shown in title block; DrawnBy: Jacob Thompson; Engineer: Not shown in title block; Organization: Not shown in title block; Address1: Not shown in title block; Address2: Not shown in title block; Address3: Not shown in title block; Address4: Not shown in title block; DocumentNumber: 3; Revision: Use project parameter SCH_Rev; SheetNumber: 2; SheetTotal: 2; PageSetup: Record=PageOptions¦CenterHorizontal=True¦CenterVertical=True¦PrintScale=1.00¦XCorrection=1.00¦YCorrection=1.00¦PrintKind=0¦BorderSize=5000000¦LeftOffset=0¦BottomOffset=0¦Orientation=2¦PaperLength=1000¦PaperWidth=1000¦Scale=100¦PaperSource=15¦PrintQuality=600¦MediaType=1¦DitherType=10¦PaperKind=Letter¦PrintScaleMode=1
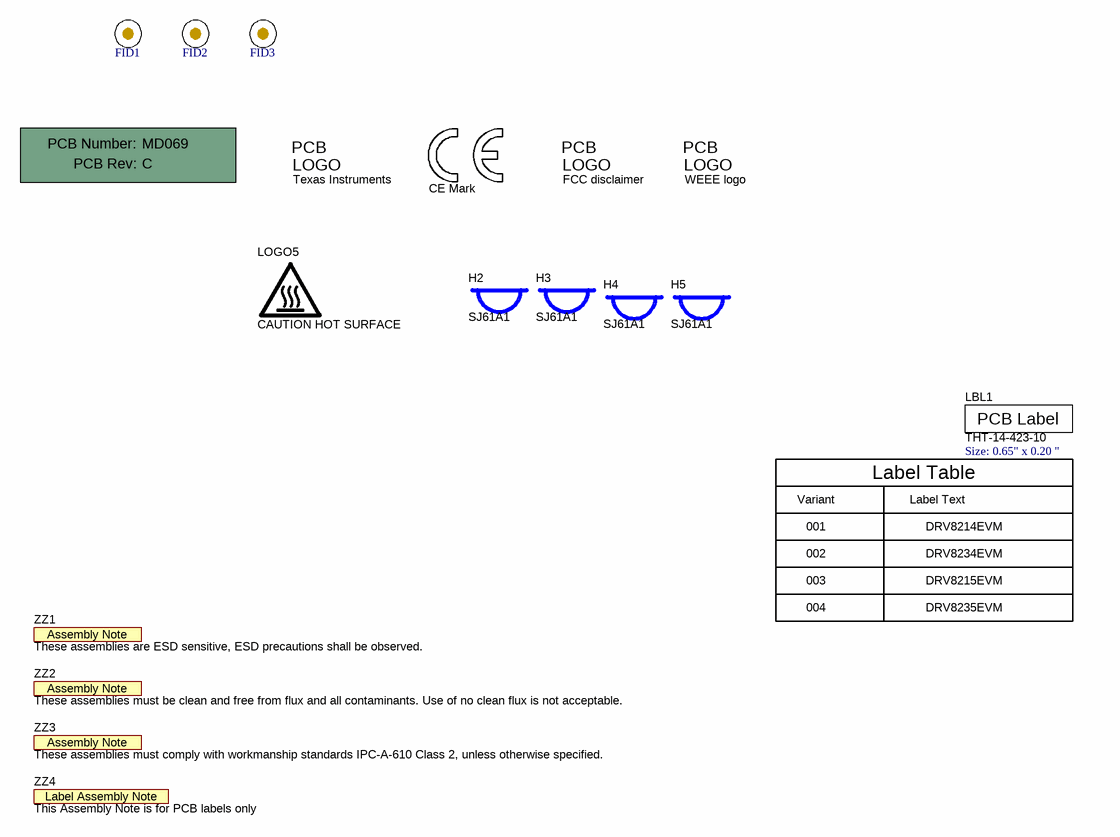
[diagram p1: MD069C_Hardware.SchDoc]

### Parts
!PCB1  Printed Circuit Board  (value not drawn)  (mechanical)
FID1  Fiducial  [Fiducial10-20]  (value not drawn)
FID2  Fiducial  [Fiducial10-20]  (value not drawn)
FID3  Fiducial  [Fiducial10-20]  (value not drawn)
H2  SJ61A1  [Bumpon_SJ61A1]
H3  SJ61A1  [Bumpon_SJ61A1]
H4  SJ61A1  [Bumpon_SJ61A1]
H5  SJ61A1  [Bumpon_SJ61A1]
LBL1  THT-14-423-10  Note: Size: 0.65" x 0.20 "  [Label_650x200]
Logo1  CE Mark  [CE_Mark_5mm]  (no BOM)
Logo2  Texas Instruments  [TI_Stacked_Overlay_Medium]  (no BOM)
Logo3  FCC disclaimer  [FCC_disclaimer]  (no BOM)
Logo4  WEEE logo  [WEEE_Minimum]  (no BOM)
LOGO5  CAUTION HOT SURFACE  [IEC_HotSurface_Small]  (no BOM)
ZZ1  These assemblies are ESD sensitive, ESD precautions shall be observed.  [AssemblyNote]  (no BOM)
ZZ2  These assemblies must be clean and free from flux and all contaminants. Use of no clean flux is not acceptable.  [AssemblyNote]  (no BOM)
ZZ3  These assemblies must comply with workmanship standards IPC-A-610 Class 2, unless otherwise specified.  [AssemblyNote]  (no BOM)
ZZ4  This Assembly Note is for PCB labels only  [AssemblyNoteLabel]  (no BOM)

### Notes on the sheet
- Variant
- 001
- Label Table
- Label Text
- DRV8214EVM
- 002
- 003
- DRV8234EVM
- DRV8215EVM
- 004
- DRV8235EVM

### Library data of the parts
!PCB1 = CMP-0003618-2: Manufacturer: Any; PartNumber: MD069
FID1-FID3 = CMP-0077181-1: Fiducial mark.  There is nothing to buy or mount.
H2-H5 = CMP-0003621-1: Bumpon, Cylindrical, 0.312 X 0.200, Black; Manufacturer: 3M
LBL1 = CMP-0003625-1: Thermal Transfer Printable Labels, 0.650" W x 0.200" H - 10,000 per roll; Manufacturer: Brady
Logo1 = CMP-0074844-1: SymbolCreator: a0412235
Logo2 = CMP-0074838-1: Texas Instrument Corporate Signature; SymbolCreator: a0412235; Lib Reference: TI_Logo
Logo3 = CMP-0074847-1: FCC_disclaimer
Logo4 = CMP-0074769-3: Manufacturer: Texas Instruments; CompType: IC; AEC Category: Q200
LOGO5 = CMP-0074837-2: IEC 61010-1 Hot Surface Warning; Manufacturer: Texas Instruments; SymbolCreator: a0412235; CompType: IC; AEC Category: Q200
ZZ1 = CMP-0077236-1
ZZ2 = CMP-0077237-1
ZZ3 = CMP-0077238-1
ZZ4 = CMP-0003616-3

## Sheet MD069C_ezFET.SchDoc
size 431 x 279 mm; Date: Not shown in title block; ApprovedBy: Not shown in title block; CheckedBy: Not shown in title block; Author: Not shown in title block; CompanyName: Not shown in title block; DrawnBy: Jacob Thompson; Engineer: Not shown in title block; Organization: Not shown in title block; Address1: Not shown in title block; Address2: Not shown in title block; Address3: Not shown in title block; Address4: Not shown in title block; DocumentNumber: 1; SheetNumber: 1; SheetTotal: 1; PageSetup: Record=PageOptions¦CenterHorizontal=True¦CenterVertical=True¦PrintScale=1.00¦XCorrection=1.00¦YCorrection=1.00¦PrintKind=0¦BorderSize=5000000¦LeftOffset=0¦BottomOffset=0¦Orientation=2¦PaperLength=1000¦PaperWidth=1000¦Scale=100¦PaperSource=15¦PrintQuality=600¦MediaType=1¦DitherType=10¦PaperKind=Letter¦PrintScaleMode=1
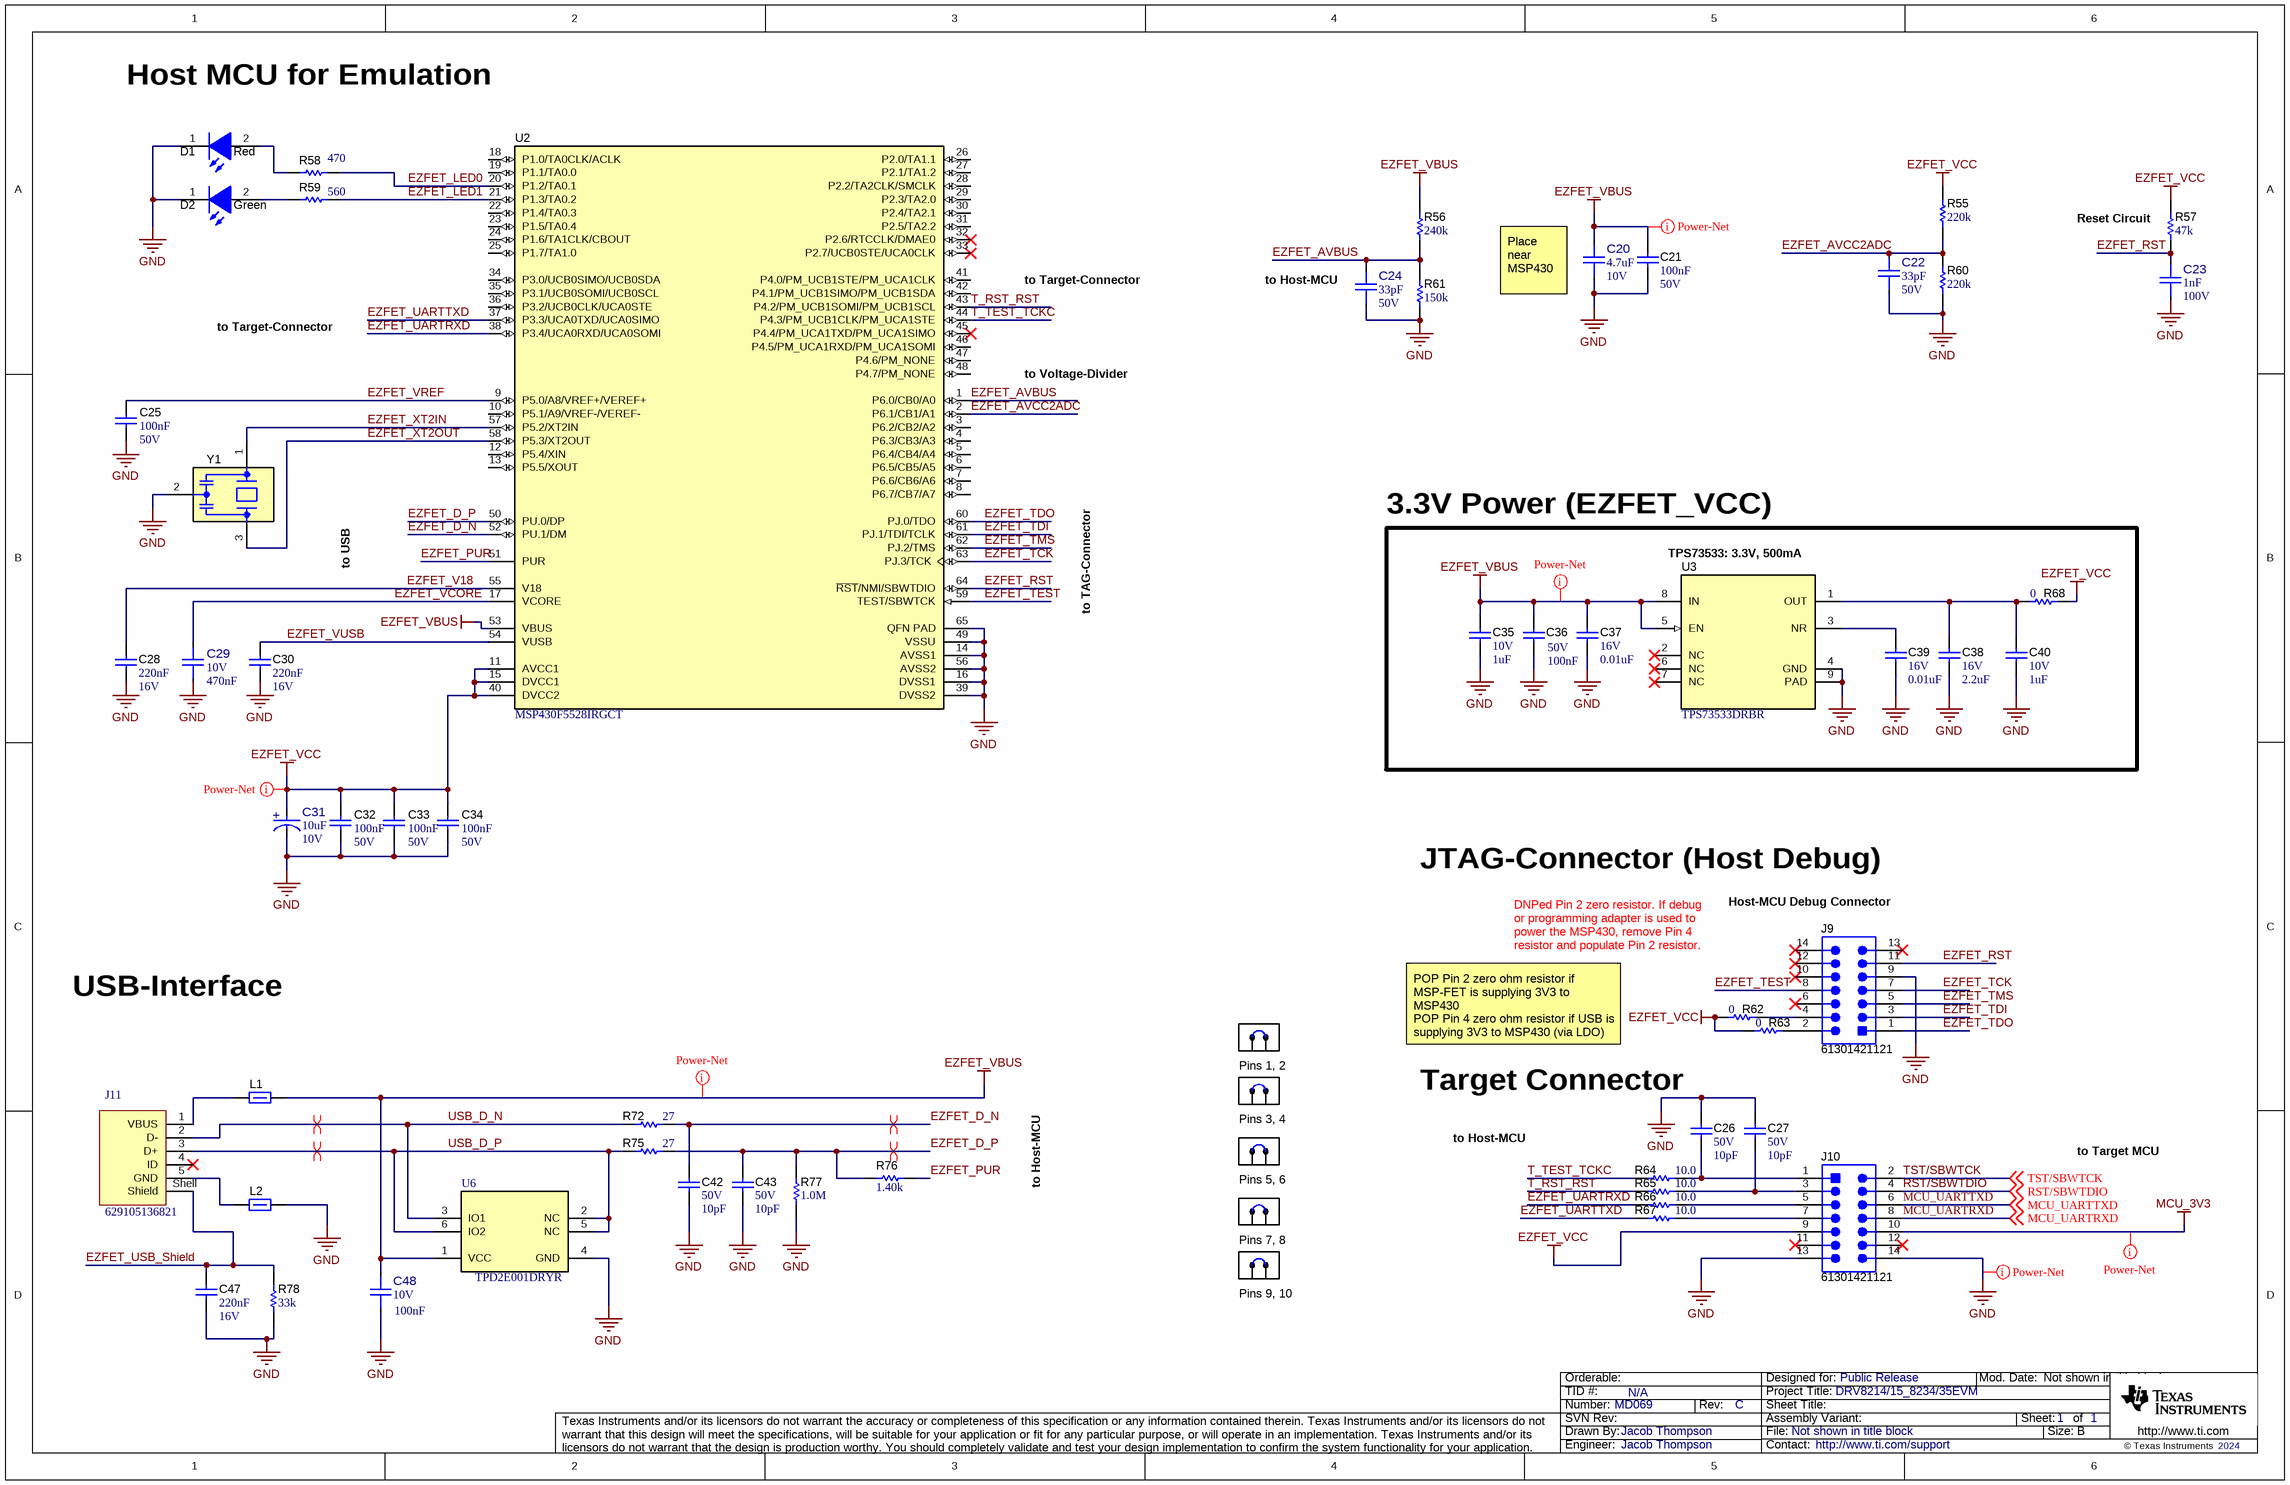
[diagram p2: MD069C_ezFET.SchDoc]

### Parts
C20  ValueDisplayed: 4.7uF  VDC_V: 10V  [FP-885012106012_0603-MFG]  (hidden comment: 885012106012)
C21  Cap_F: 100nF  VDC_V: 50V  [0603]  (hidden comment: 885012206095)
C22  ValueDisplayed: 33pF  VDC_V: 50V  [FP-885012005058_0402-MFG]  (hidden comment: 885012005058)
C23  ValueDisplayed: 1nF  VDC_V: 100V  [FP-885012006085_0603-MFG]  (hidden comment: 885012006085)
C24  ValueDisplayed: 33pF  VDC_V: 50V  [FP-885012005058_0402-MFG]  (hidden comment: 885012005058)
C25  Cap_F: 100nF  VDC_V: 50V  [0603]  (hidden comment: 885012206095)
C26  VDC_V: 50V  ValueDisplayed: 10pF  [0402]  (hidden comment: 885012005055)
C27  VDC_V: 50V  ValueDisplayed: 10pF  [0402]  (hidden comment: 885012005055)
C28  Cap_F: 220nF  VDC_V: 16V  [0603]  (hidden comment: 885012206048)
C29  ValueDisplayed: 470nF  VDC_V: 10V  [FP-885012106008_0603-MFG]  (hidden comment: 885012106008)
C30  Cap_F: 220nF  VDC_V: 16V  [0603]  (hidden comment: 885012206048)
C31  ValueDisplayed: 10uF  VDC_V: 10V  [FP-875105240001_SMT_CAP_4MM3_4MM3-MFG]  (hidden comment: 875105240001)
C32  Cap_F: 100nF  VDC_V: 50V  [0603]  (hidden comment: 885012206095)
C33  Cap_F: 100nF  VDC_V: 50V  [0603]  (hidden comment: 885012206095)
C34  Cap_F: 100nF  VDC_V: 50V  [0603]  (hidden comment: 885012206095)
C35  VDC_V: 10V  ValueDisplayed: 1uF  [0402]  (hidden comment: 885012105012)
C36  Cap_F: 100nF  VDC_V: 50V  [0603]  (hidden comment: 885012206095)
C37  VDC_V: 16V  ValueDisplayed: 0.01uF  [0402]  (hidden comment: 885012205031)
C38  VDC_V: 16V  ValueDisplayed: 2.2uF  [0603]  (hidden comment: 885012106018)
C39  VDC_V: 16V  ValueDisplayed: 0.01uF  [0402]  (hidden comment: 885012205031)
C40  VDC_V: 10V  ValueDisplayed: 1uF  [0402]  (hidden comment: 885012105012)
C42  VDC_V: 50V  ValueDisplayed: 10pF  [0402]  (hidden comment: 885012005055)
C43  VDC_V: 50V  ValueDisplayed: 10pF  [0402]  (hidden comment: 885012005055)
C47  Cap_F: 220nF  VDC_V: 16V  [0603]  (hidden comment: 885012206048)
C48  value 100nF  VDC_V: 10V  [FP-885012205018_0402-MFG]  (hidden comment: 885012205018)
D1  value Red  [WL-SMCW_RED]  (hidden comment: 150060RS75000)
D2  value Green  [WL-SMCW_GREEN]  (hidden comment: 150060VS75000)
J9  61301421121  [Wurth_61301421121]
J10  61301421121  [Wurth_61301421121]
J11  629105136821  [629105136821]
L1  742792621  [0603L]  (value not drawn)
L2  742792621  [0603L]  (value not drawn)
R55  ValueDisplayed: 220k  [0402]  (hidden comment: RC0402FR-07220KL)
R56  ValueDisplayed: 240k  [0402]  (hidden comment: CRCW0402240KFKED)
R57  ValueDisplayed: 47k  [0402]  (hidden comment: CRCW040247K0JNED)
R58  ValueDisplayed: 470  [0603]  (hidden comment: RC0603JR-07470RL)
R59  ValueDisplayed: 560  [0603]  (hidden comment: RC0603JR-07560RL)
R60  ValueDisplayed: 220k  [0402]  (hidden comment: RC0402FR-07220KL)
R61  ValueDisplayed: 150k  [0402]  (hidden comment: CRCW0402150KFKED)
R62  value 0  [0603L]  (hidden comment: Resistor)
R63  value 0  [0603L]  (hidden comment: Resistor)
R64  ValueDisplayed: 10.0  [0402]  (hidden comment: CRCW040210R0FKED)
R65  ValueDisplayed: 10.0  [0402]  (hidden comment: CRCW040210R0FKED)
R66  ValueDisplayed: 10.0  [0402]  (hidden comment: CRCW040210R0FKED)
R67  ValueDisplayed: 10.0  [0402]  (hidden comment: CRCW040210R0FKED)
R68  value 0  [0603L]  (hidden comment: Resistor)
R72  ValueDisplayed: 27  [0402L]  (hidden comment: CRCW040227R0JNED)
R75  ValueDisplayed: 27  [0402L]  (hidden comment: CRCW040227R0JNED)
R76  ValueDisplayed: 1.40k  [0402L]  (hidden comment: CRCW04021K40FKED)
R77  ValueDisplayed: 1.0M  [0402L]  (hidden comment: CRCW04021M00JNED)
R78  ValueDisplayed: 33k  [0402S]  (hidden comment: CRCW040233K0JNED)
SH-J29  60900213421  [Wurth_60900213421]  (value not drawn)
SH-J31  60900213421  [Wurth_60900213421]  (value not drawn)
SH-J32  60900213421  [Wurth_60900213421]  (value not drawn)
SH-J33  60900213421  [Wurth_60900213421]  (value not drawn)
SH-J34  60900213421  [Wurth_60900213421]  (value not drawn)
U2  MSP430F5528IRGCT  [RGC0064B]
U3  TPS73533DRBR  [DRB0008A]
U6  TPD2E001DRYR  [DRY0006A]
Y1  CSTNR4M00GH5L000R0  [MuRata_CSTNR]  (value not drawn)

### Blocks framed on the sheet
3.3V Power (EZFET_VCC): C35-C40 R68 U3

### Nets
EZFET_VBUS: C20.2 C21.1 C35.1 C36.1 C37.1 C48.2 L1.2 R56.2 U2.53(VBUS) U3.5(EN) U3.8(IN) U6.1(VCC)
EZFET_VCC: C31.2(ANODE) C32.1 C33.1 C34.1 J10.9 R55.2 R57.2 R62.2 R63.2 R68.1 U2.11(AVCC1) U2.15(DVCC1) U2.40(DVCC2)
GND: C20.1 C21.2 C22.1 C23.1 C24.1 C25.2 C26.1 C27.1 C28.2 C29.1 C30.2 C31.1(CATHODE) C32.2 C33.2 C34.2 C35.2 C36.2 C37.2 C38.2 C39.2 C40.2 C42.2 C43.2 C47.2 C48.1 D1.1(K) D2.1(K) J9.9 J10.13 J10.14 L2.2 R60.1 R61.1 R77.1 R78.1 U2.14(AVSS1) U2.16(DVSS1) U2.39(DVSS2) U2.49(VSSU) U2.56(AVSS2) U2.65(QFN_PAD) U3.4(GND) U3.9(PAD) U6.4(GND) Y1.2(GND)
MCU_3V3: J10.10
EZFET_AVBUS: C24.2 R56.1 R61.2 U2.1(P6.0/CB0/A0)
EZFET_AVCC2ADC: C22.2 R55.1 R60.2 U2.2(P6.1/CB1/A1)
EZFET_D_N: C42.1 R72.2 U2.52(PU.1/DM)
EZFET_D_P: C43.1 R75.2 R76.1 R77.2 U2.50(PU.0/DP)
EZFET_LED0: R58.1 U2.20(P1.2/TA0.1)
EZFET_LED1: R59.1 U2.21(P1.3/TA0.2)
EZFET_PUR: R76.2 U2.51(PUR)
EZFET_RST: C23.2 J9.11 R57.1 U2.64(~{RST}/NMI/SBWTDIO)
EZFET_TCK: J9.7 U2.63(PJ.3/TCK)
EZFET_TDI: J9.3 U2.61(PJ.1/TDI/TCLK)
EZFET_TDO: J9.1 U2.60(PJ.0/TDO)
EZFET_TEST: J9.8 U2.59(TEST/SBWTCK)
EZFET_TMS: J9.5 U2.62(PJ.2/TMS)
EZFET_UARTRXD: R66.1 U2.38(P3.4/UCA0RXD/UCA0SOMI)
EZFET_UARTTXD: R67.1 U2.37(P3.3/UCA0TXD/UCA0SIMO)
EZFET_USB_Shield: C47.1 J11.Shell(Shield) R78.2
EZFET_V18: C28.1 U2.55(V18)
EZFET_VCORE: C29.2 U2.17(VCORE)
EZFET_VREF: C25.1 U2.9(P5.0/A8/VREF+/VEREF+)
EZFET_VUSB: C30.1 U2.54(VUSB)
EZFET_XT2IN: U2.57(P5.2/XT2IN) Y1.1(In)
EZFET_XT2OUT: U2.58(P5.3/XT2OUT) Y1.3(Out)
MCU_UARTRXD: J10.8 ; off-sheet MCU_UARTRXD
MCU_UARTTXD: J10.6 ; off-sheet MCU_UARTTXD
RST/SBWTDIO: J10.4 ; off-sheet RST/SBWTDIO
T_RST_RST: R65.1 U2.43(P4.2/PM_UCB1SOMI/PM_UCB1SCL)
T_TEST_TCKC: R64.1 U2.44(P4.3/PM_UCB1CLK/PM_UCA1STE)
TST/SBWTCK: J10.2 ; off-sheet TST/SBWTCK
USB_D_N: J11.2(D-) R72.1 U6.3(IO1)
USB_D_P: J11.3(D+) R75.1 U6.2(NC) U6.5(NC) U6.6(IO2)
NetC26_2: C26.2 J10.1 R64.2
NetC27_2: C27.2 J10.3 R65.2
NetC38_1: C38.1 C40.1 R68.2 U3.1(OUT)
NetC39_1: C39.1 U3.3(NR)
NetD1_2: D1.2(A) R58.2
NetD2_2: D2.2(A) R59.2
NetJ9_2: J9.2 R63.1
NetJ9_4: J9.4 R62.1
NetJ10_5: J10.5 R66.2
NetJ10_7: J10.7 R67.2
NetJ11_1: J11.1(VBUS) L1.1
NetJ11_5: J11.5(GND) L2.1

Not connected (* = marked no-connect by the designer): J9 6* 10* 12* 13* 14*; J10 11* 12*; J11 4(ID)*; U2 3(P6.2/CB2/A2) 4(P6.3/CB3/A3) 5(P6.4/CB4/A4) 6(P6.5/CB5/A5) 7(P6.6/CB6/A6) 8(P6.7/CB7/A7) 10(P5.1/A9/VREF-/VEREF-) 12(P5.4/XIN) 13(P5.5/XOUT) 18(P1.0/TA0CLK/ACLK) 19(P1.1/TA0.0) 22(P1.4/TA0.3) 23(P1.5/TA0.4) 24(P1.6/TA1CLK/CBOUT) 25(P1.7/TA1.0) 26(P2.0/TA1.1) 27(P2.1/TA1.2) 28(P2.2/TA2CLK/SMCLK) 29(P2.3/TA2.0) 30(P2.4/TA2.1) 31(P2.5/TA2.2) 32(P2.6/RTCCLK/DMAE0)* 33(P2.7/UCB0STE/UCA0CLK)* 34(P3.0/UCB0SIMO/UCB0SDA) 35(P3.1/UCB0SOMI/UCB0SCL) 36(P3.2/UCB0CLK/UCA0STE) 41(P4.0/PM_UCB1STE/PM_UCA1CLK) 42(P4.1/PM_UCB1SIMO/PM_UCB1SDA) 45(P4.4/PM_UCA1TXD/PM_UCA1SIMO)* 46(P4.5/PM_UCA1RXD/PM_UCA1SOMI) 47(P4.6/PM_NONE) 48(P4.7/PM_NONE); U3 2(NC)* 6(NC)* 7(NC)*

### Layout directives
net class Power-Net: EZFET_VBUS, EZFET_VCC, GND, MCU_3V3
differential pair: EZFET_D_N, EZFET_D_P, USB_D_N, USB_D_P

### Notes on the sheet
- Host MCU for Emulation
- (near R57) Reset Circuit
- to Target-Connector
- (near C24) to Host-MCU
- (near C20) Place near MSP430
- to Voltage-Divider
- to USB
- to TAG-Connector
- (near U3) TPS73533: 3.3V, 500mA
- JTAG-Connector (Host Debug)
- DNPed Pin 2 zero resistor. If debug or programming adapter is used to power the MSP430, remove Pin 4 resistor and populate Pin 2 resistor.
- (near J9) Host-MCU Debug Connector
- USB-Interface
- Pins 1, 2
- POP Pin 2 zero ohm resistor if MSP-FET is supplying 3V3 to MSP430
  POP Pin 4 zero ohm resistor if USB is supplying 3V3 to MSP430 (via LDO)
- Target Connector
- to Host-MCU
- Pins 3, 4
- to Target MCU
- Pins 5, 6
- Pins 7, 8
- (near SH-J34) Pins 9, 10

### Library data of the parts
C20 = CMP-0097305-1: 4.7 µF ±20% 10V Ceramic Capacitor X5R 0603 (1608 Metric); Manufacturer: Wurth Electronics; Cap_F: 4.7µF; Value: 4.7µF; AEC Qualified: No; SizeZ_mm: 0.87mm; TempCo: 15%
C21 C25 C32-C34 C36 = CMP-0006837-4: as C6 on sheet MD069C
C22 C24 = CMP-0097306-1: 33 pF ±5% 50V Ceramic Capacitor C0G, NP0 0402 (1005 Metric); Manufacturer: Wurth Electronics; AEC Qualified: No; Value: 33pF; TempCo: 30ppm/°C; SizeZ_mm: 0.55mm
C23 = CMP-0097311-1: as C41 on sheet MD069C
C26 C27 C42 C43 = CMP-0006215-2: as C44 on sheet MD069C
C28 C30 C47 = CMP-0006830-4: CAP, CERM, 0.22 uF, 16 V, +/- 10%, X7R, 0603; Manufacturer: Wurth Elektronik; TaMin_C: -55°C; Polarized: N; SizeAreaWB_mm2: 4.68; Value1: Unknown; U/M: EA; Value: 0.22uF; TaMax_C: 125°C; SizeZ_mm: 1; SizeX_mm: 1.6; SizeY_mm: 0.8; SizeArea_mm2: 1.28; AEC Category: Q200
C29 = CMP-0097299-1: as C49 on sheet MD069C
C31 = CMP-0097340-1: as C51 on sheet MD069C
C35 C40 = CMP-0064924-2: CAP, CERM, 1 uF, 10 V,+/- 20%, X5R, 0402; Manufacturer: Wurth Elektronik; TaMin_C: -55°C; Polarized: N; SizeAreaWB_mm2: 3; Value1: Unknown; U/M: EA; Value: 1uF; TaMax_C: 85°C; SizeZ_mm: 0.6; SizeX_mm: 1; SizeY_mm: 0.5; Cap_F: 1µF; AEC Category: Q200
C37 C39 = CMP-0006227-2: CAP, CERM, 0.01 uF, 16 V, +/- 10%, X7R, 0402; Manufacturer: Wurth Elektronik; TaMin_C: -55°C; Polarized: N; SizeAreaWB_mm2: 3; Value1: Unknown; U/M: EA; Value: 0.01uF; TaMax_C: 125°C; SizeZ_mm: 0.6; SizeX_mm: 1; SizeY_mm: 0.5; Cap_F: 10nF; AEC Category: Q200
C38 = CMP-0006825-5: CAP, CERM, 2.2 uF, 16 V, +/- 20%, X5R, 0603; Manufacturer: Wurth Elektronik; TaMin_C: -55°C; Polarized: N; SizeAreaWB_mm2: 4.68; Value1: Unknown; U/M: EA; Value: 2.2uF; TaMax_C: 85°C; SizeZ_mm: 1; SizeX_mm: 1.6; SizeY_mm: 0.8; SizeArea_mm2: 1.28; Cap_F: 2.2µF; AEC Category: Q200
C48 = CMP-0090362-1: 0.1µF ±10% 10V Ceramic Capacitor X7R 0402 (1005 Metric); Manufacturer: Wurth Electronics; AEC Qualified: No; SizeZ_mm: 0.55mm; ValueDisplayed: 100000pF; TempCo: 15%
D1 = CMP-0002947-3: LED, Red, SMD; Manufacturer: Wurth Elektronik; Type: AlInGaP; Vf_V: 2V; Io_A: 30mA; Vr_V: 5V; Tjmax_C: 85°C; Power_TotalModule: 72mW; Value1: 0.072W; Angle: 140
D2 = CMP-0002894-2: LED, Green, SMD; Manufacturer: Wurth Elektronik; Type: AlInGaP; Vf_V: 2V; Io_A: 20mA; Value1: W
J9 J10 = CMP-0086014-1: Header, 2.54mm, 7x2, Gold, TH; Manufacturer: Wurth Elektronik; Pitch_mm: 2.54; Voltage_V: 250V; Shrouded: N; Gender: Male; Current_A: 3A; Cert_UL: Y; Row_Count: 2
J11 = CMP-1502-03253-2: USB - micro B USB 2.0 Receptacle Connector 5 Position Surface Mount, Right Angle; NexarPartId: 19991173; Manufacturer: Wurth Elektronik; Contact Resistance: 30mΩ; Insulation Resistance: 1GΩ; Number of Contacts: 5; Number of Ports: 1; Current Rating: 1A; Voltage Rating: 30V; USB Standard: USB 2.0; Plating: Nickel
L1 L2 = CMP-0003184-2: Ferrite Bead, 140 ohm @ 100 MHz, 0.55 A, 0603; Manufacturer: Wurth Elektronik; Ztyp@1GHz_Ohm: 271.401; ZTyp@100MHz_Ohm: 140; SizeAreaWB_mm2: 4.68; DCR_ohm: 0.2; Value1: 0.2 ohm; Value: 140 ohm; Imax_A: 550mA; SizeZ_mm: 1; SizeX_mm: 1.6; SizeY_mm: 0.8; Value2: 0.55A; SizeArea_mm2: 1.28
R55 R60 = CMP-0026728-1: RES, 220 k, 1%, 0.0625 W, 0402; Manufacturer: Yageo America; Power_W: 62.5mW; TempCo: 100 ppm/C; U/M: EA; Value: 220k; SizeX_mm: 1; SizeY_mm: 0.5; SizeZ_mm: 0.6; AEC Qualified: N; VDC_V: 50V; AEC Category: Q200
R56 = CMP-0026190-2: RES, 240 k, 1%, 0.063 W, AEC-Q200 Grade 0, 0402; Manufacturer: Vishay-Dale; Power_W: 63mW; TempCo: 100 ppm/C; Value: 240k; SizeX_mm: 1; SizeY_mm: 0.5; SizeZ_mm: 0.6; Value2: 0.063W; AEC Qualified: Y; VDC_V: 50V; AEC Category: Q200; AEC Grade: 0
R57 = CMP-0026935-3: as R18 on sheet MD069C
R58 = CMP-0025924-5: RES, 470, 5%, 0.1 W, 0603; Manufacturer: Yageo; Power_W: 100mW; TempCo: 100 ppm/C; Value_Code: 470R; Value: 470; EIA_Code: E24; SizeX_mm: 1.6; SizeY_mm: 0.8; SizeZ_mm: 1; Value2: 0.1W; SizeArea_mm2: 1.28; AEC Qualified: N; VDC_V: 75V; AEC Category: Q200; SizeAreaWB_mm2: 4.68
R59 = CMP-0025930-5: as R42 on sheet MD069C
R61 = CMP-0026021-3: RES, 150 k, 1%, 0.063 W, AEC-Q200 Grade 0, 0402; Manufacturer: Vishay-Dale; Power_W: 63mW; TempCo: 100 ppm/C; Value: 150k; EIA_Code: E96; SizeX_mm: 1; SizeY_mm: 0.5; SizeZ_mm: 0.6; Value2: 0.063W; AEC Qualified: Y; VDC_V: 50V; AEC Category: Q200; AEC Grade: 0
R62 R63 R68 = CMP-0025697-4: as R3 on sheet MD069C
R64-R67 = CMP-0025963-3: as R9 on sheet MD069C
R72 R75 = CMP-0026888-3: RES, 27, 5%, 0.063 W, AEC-Q200 Grade 0, 0402; Manufacturer: Vishay-Dale; Power_W: 63mW; TempCo: 200 ppm/C; Value_Code: 27R0; Value: 27; EIA_Code: E24; SizeX_mm: 1; SizeY_mm: 0.5; SizeZ_mm: 0.6; Value2: 0.063W; AEC Qualified: Y; VDC_V: 50V; AEC Category: Q200; AEC Grade: 0
R76 = CMP-0026085-3: RES, 1.40 k, 1%, 0.063 W, AEC-Q200 Grade 0, 0402; Manufacturer: Vishay-Dale; Power_W: 63mW; TempCo: 100 ppm/C; Value_Code: 1k40; Value: 1.40k; EIA_Code: E96; Res_ohm: 1.4k; SizeX_mm: 1; SizeY_mm: 0.5; SizeZ_mm: 0.6; Value2: 0.063W; AEC Qualified: Y; VDC_V: 50V; AEC Category: Q200; AEC Grade: 0
R77 = CMP-0026859-2: RES, 1.0 M, 5%, 0.063 W, AEC-Q200 Grade 0, 0402; Manufacturer: Vishay-Dale; Power_W: 63mW; TempCo: 200 ppm/C; Value_Code: 1M00; Value: 1.0Meg; EIA_Code: E24; Res_ohm: 1M; SizeX_mm: 1; SizeY_mm: 0.5; SizeZ_mm: 0.6; Value2: 0.063W; AEC Qualified: Y; VDC_V: 50V; AEC Category: Q200; AEC Grade: 0
R78 = CMP-0026907-3: RES, 33 k, 5%, 0.063 W, AEC-Q200 Grade 0, 0402; Manufacturer: Vishay-Dale; Power_W: 63mW; TempCo: 200 ppm/C; Value_Code: 33k0; Value: 33k; EIA_Code: E24; SizeX_mm: 1; SizeY_mm: 0.5; SizeZ_mm: 0.6; Value2: 0.063W; AEC Qualified: Y; VDC_V: 50V; AEC Category: Q200; AEC Grade: 0
SH-J29 SH-J31-SH-J34 = CMP-0003761-2: as SH-J1 on sheet MD069C
U2 = CMP-0039269-4: 16-Bit Ultra-Low-Power Microcontroller, 128KB Flash, 8KB RAM, USB, 12Bit ADC, 2 USCIs, 32Bit HW MPY, RGC0064B (VQFN-64); Alternate Manufacturer: Texas Instruments; Alternate PartNumber: MSP430F5528IRGCR; ADC: 12-bit SAR; ADC Channels: 16; Brown Out Reset: Yes; DMA: 3; Flash(KB): 128; Frequency(MHz): 25; GPIO: 47; Multiplier: 32x32; SRAM(B): 8192; Timers - 16-bit: 4; USB: 1; USCI_A (UART/LIN/IrDA/SPI): 2; Rating: Catalog; SizeArea_mm2: 81.0; SizeZ_mm: 1.0; Green_REACh: Passed; AEC Qualified: N; AEC Category: Q200; CompType: IC; Green_Lifecycle: Active; SizeY_mm: 9.0; SizeAreaWB_mm2: 121.0
U3 = CMP-0036328-3: 500mA, Adjustable, Low Quiescent Current, Low-Noise, High-PSRR, Single-Output LDO Regulator, DRB0008A (VSON-8); Manufacturer: Texas Instruments; CompType: IC; Green_Lifecycle: Active; SizeZ_mm: 1.0; Iq(Typ)(mA): 0.04; SizeY_mm: 3.0; SizeAreaWB_mm2: 16.0; SizeArea_mm2: 9.0; AEC Category: Q200; Vout Adj(Max)(V): 3.3; AEC Qualified: N; Accuracy(%): 2; Vin(Max)(V): 6.5; Vdo(Typ)(mV): 280; Iout(Max)(A): 0.5; Green_REACh: Passed; Rating: Catalog; Vin(Min)(V): 2.7
U6 = CMP-0043099-3: Low-Capacitance 2-Channel +/-15kV ESD Protection Array for High-Speed Data Interfaces, DRY0006A (USON-6); Manufacturer: Texas Instruments; IO Leakage Current(nA): 1; IEC 61000-4-2 Air-Gap(+/- kV): 15; USB High Speed: TRUE; IO Capacitance(Typ)(pF): 1.5; Eco-Plan: Green (RoHS & no Sb/Br); Breakdown Voltage(Min)(V): 11; IEC 61000-4-2 Contact(+/- kV): 8; AEC Category: Q200; AEC Qualified: N; CompType: IC; SizeAreaWB_mm2: 4.9; SizeArea_mm2: 1.45; SizeX_mm: 1.0; SizeZ_mm: 0.6; Rating: Catalog
Y1 = CMP-0085483-1: Oscillator, 4 MHz, 700 ppm, 39 pF, SMD; Manufacturer: MuRata; SizeArea_mm2: 9; Load Capacitance: 39 pF; SizeZ_mm: 1.2; AEC Category: Q200; Frequency Tolerance: 700 ppm; SizeX_mm: 4.5; SizeAreaWB_mm2: 16.5; TaMax_C: 85°C; TaMin_C: -20°C; SizeY_mm: 2; AEC Qualified: N; Frequency_Fixed: 4MHz

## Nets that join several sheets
GND: MD069C (68 pins), MD069C_ezFET (45 pins)
MCU_3V3: MD069C (22 pins), MD069C_ezFET (J10.10)
MCU_UARTRXD: MD069C (U1.61), MD069C_ezFET (J10.8)
MCU_UARTTXD: MD069C (U1.60), MD069C_ezFET (J10.6)
RST/SBWTDIO: MD069C (6 pins), MD069C_ezFET (J10.4)
TST/SBWTCK: MD069C (U1.91), MD069C_ezFET (J10.2)

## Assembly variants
001: not fitted C4 C5 C6 C7 C8 C44 C45 C57 C58 R3 R4 R12 R13 R14 R40 R51 R53 R62 U4 Y2
002: not fitted C4 C5 C6 C7 C8 C44 C45 C57 C58 R3 R4 R5 R13 R14 R39 R40 R53 R62 U4 Y2; alternate parts U5 -> CMP-0097574-1
003: not fitted C4 C5 C6 C7 C8 C44 C45 C57 C58 R3 R4 R12 R13 R14 R39 R52 R53 R62 SH-J29 U4 Y2; alternate parts U5 -> CMP-0121104-2
004: not fitted C4 C5 C6 C7 C8 C44 C45 C57 C58 R3 R4 R5 R13 R14 R39 R40 R51 R53 R62 SH-J29 U4 Y2; alternate parts U5 -> CMP-0121105-2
